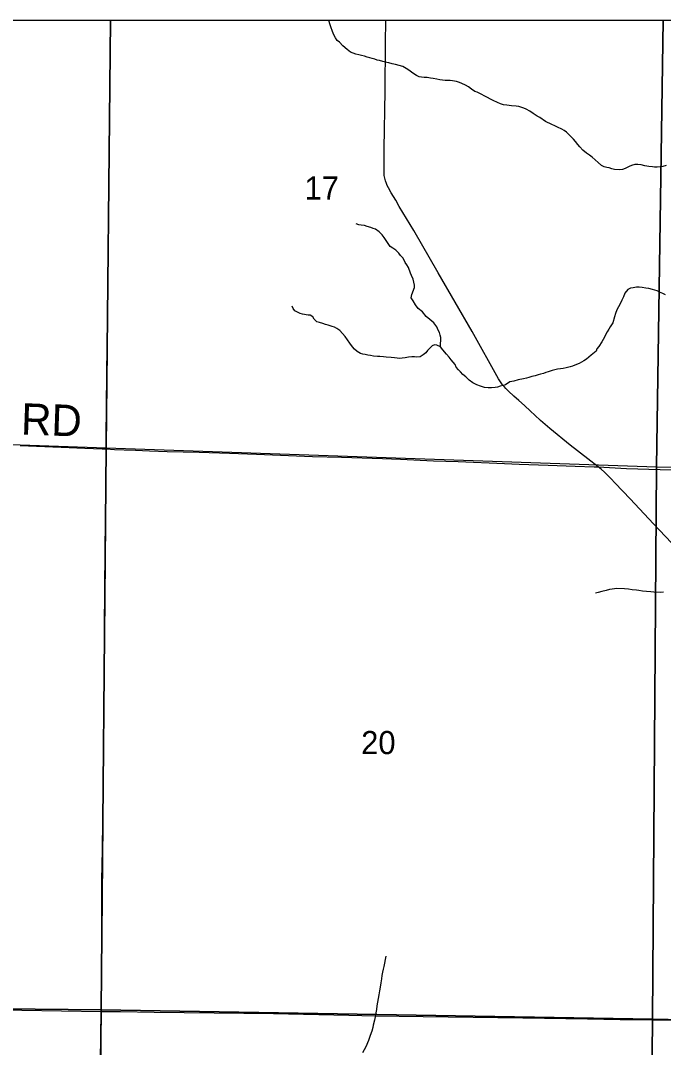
# Model space of a CAD drawing. Extents: x 0 to 34, y 0 to 22.
# Drawn here: x 27.506 to 28.088, y 19.307 to 20.236 of the extents above; entities that cross this region are included whole.
import ezdxf

# ---------------------------------------------------------------- set-up
doc = ezdxf.new("R2010")
doc.units = 0
for name, color, linetype in [('GM_X_Minor_River', 7, 'Continuous'), ('GM_X_Section', 7, 'Continuous'), ('GM_X_Section_Text', 7, 'Continuous'), ('GM_X_Township_Road', 7, 'Continuous'), ('GM_X_Township_Road_Text', 7, 'Continuous'), ('GM_X_Unincorporated', 7, 'Continuous'), ('SC_Scratch1', 7, 'Continuous'), ('SH_Border', 7, 'Continuous'), ('SH_Cut_Line', 7, 'Continuous')]:
    doc.layers.add(name, color=color, linetype=linetype)

msp = doc.modelspace()

# ---------------------------------------------------------------- linework, layer by layer
at = {"layer": 'GM_X_Minor_River'}
for points in [[(27.82658, 20.2012), (27.82431, 20.20183), (27.82224, 20.20245), (27.81978, 20.20309), (27.81714, 20.20391), (27.8145, 20.20455), (27.81224, 20.20518), (27.80959, 20.20582), (27.80695, 20.20664), (27.80451, 20.20766), (27.80153, 20.21001), (27.79762, 20.21316), (27.79466, 20.21646), (27.79261, 20.21804), (27.79096, 20.22036), (27.78951, 20.22306), (27.78846, 20.22632), (27.78685, 20.23055), (27.78578, 20.23305), (27.78546, 20.23534), (27.78502, 20.23613)], [(28.08999, 20.10513), (28.08711, 20.10406), (28.08463, 20.10375), (28.08196, 20.10343), (28.07968, 20.10349), (28.0776, 20.10392), (28.07438, 20.1042), (28.07078, 20.10486), (28.06738, 20.10552), (28.06454, 20.10597), (28.06188, 20.10604), (28.05881, 20.10497), (28.0567, 20.10408), (28.05304, 20.10227), (28.05073, 20.10137), (28.04769, 20.10107), (28.04352, 20.10156), (28.04106, 20.102), (28.03861, 20.10282), (28.03634, 20.10326), (28.03407, 20.1037), (28.03163, 20.10509), (28.02847, 20.10784), (28.02328, 20.11253), (28.02066, 20.1145), (28.01805, 20.11628), (28.01489, 20.11902), (28.01211, 20.12176), (28.01027, 20.12408), (28.00805, 20.12661), (28.00621, 20.12875), (28.00307, 20.13225), (27.99991, 20.13519), (27.99786, 20.13657), (27.9958, 20.13776), (27.99186, 20.13977), (27.98942, 20.14078), (27.9866, 20.14199), (27.98097, 20.1448), (27.97574, 20.14835), (27.97349, 20.14974), (27.96994, 20.15211), (27.96695, 20.15409), (27.96358, 20.15608), (27.96151, 20.15689), (27.95944, 20.15751), (27.95699, 20.15834), (27.95453, 20.15859), (27.95036, 20.15908), (27.946, 20.15957), (27.94297, 20.16002), (27.94033, 20.16085), (27.93751, 20.16206), (27.93357, 20.16388), (27.92607, 20.16787), (27.92288, 20.16966), (27.91931, 20.17128), (27.91705, 20.17209), (27.91406, 20.17407), (27.91145, 20.17604), (27.90864, 20.17763), (27.90545, 20.17924), (27.9032, 20.18024), (27.90037, 20.18088), (27.89697, 20.18173), (27.89488, 20.18197), (27.89241, 20.18185), (27.89032, 20.1819), (27.88785, 20.18215), (27.8854, 20.1826), (27.88256, 20.18324), (27.87953, 20.18369), (27.87688, 20.18414), (27.87404, 20.1846), (27.87138, 20.18466), (27.86892, 20.18491), (27.86684, 20.18535), (27.8644, 20.18636), (27.86178, 20.18795), (27.85972, 20.18952), (27.85749, 20.19129), (27.85487, 20.19288), (27.85206, 20.19447), (27.84867, 20.19551), (27.84546, 20.19635), (27.84243, 20.197), (27.83941, 20.19783), (27.83733, 20.19808), (27.83394, 20.19911), (27.83073, 20.19996), (27.82865, 20.20039), (27.82658, 20.2012)], [(27.99455, 19.92122), (27.99188, 19.9209), (27.98709, 19.9195), (27.98345, 19.91846), (27.98135, 19.91775), (27.97905, 19.91705), (27.97656, 19.91635), (27.97445, 19.91564), (27.97176, 19.91476), (27.96871, 19.91408), (27.96603, 19.91338), (27.96373, 19.91268), (27.96105, 19.91218), (27.95628, 19.91116), (27.95226, 19.91012), (27.94862, 19.90926), (27.94495, 19.9067), (27.94284, 19.90618), (27.93997, 19.90549), (27.93748, 19.9046), (27.93538, 19.90428), (27.93214, 19.90398), (27.9291, 19.90387), (27.92588, 19.90433), (27.92229, 19.90537), (27.9189, 19.9066), (27.91515, 19.90859), (27.91198, 19.91095), (27.90883, 19.91389), (27.90622, 19.91604), (27.9042, 19.91857), (27.90215, 19.92033), (27.90031, 19.92266), (27.89923, 19.92497), (27.89574, 19.92943), (27.89371, 19.93176), (27.89131, 19.93448), (27.88817, 19.93818), (27.88597, 19.94108), (27.88603, 19.94374), (27.88631, 19.94697), (27.88637, 19.94944), (27.88586, 19.95173), (27.88497, 19.95404), (27.88389, 19.95616), (27.88263, 19.95904), (27.88007, 19.96272), (27.87635, 19.96585), (27.87318, 19.9684), (27.86968, 19.97268), (27.86596, 19.97581), (27.86338, 19.97911), (27.86139, 19.98277), (27.85955, 19.98529), (27.86021, 19.98851), (27.86246, 19.99472), (27.86251, 19.99681), (27.86133, 20.00236), (27.85989, 20.00544), (27.859, 20.00774), (27.85722, 20.01273), (27.85557, 20.01505), (27.85411, 20.01718), (27.85231, 20.02122), (27.84991, 20.02375), (27.84844, 20.02588), (27.84547, 20.02843), (27.84285, 20.03021), (27.84061, 20.03178), (27.83859, 20.0345), (27.83695, 20.0372), (27.83493, 20.03991), (27.83328, 20.04224), (27.83069, 20.04496), (27.82714, 20.04734), (27.82507, 20.04815), (27.823, 20.04896), (27.81961, 20.05), (27.81734, 20.05063), (27.81431, 20.05108), (27.81223, 20.05133), (27.80978, 20.05215)], [(28.08942, 19.98801), (28.08698, 19.98921), (28.08416, 19.99061), (28.08191, 19.99162), (28.07776, 19.99287), (28.07436, 19.99372), (28.07171, 19.99416), (28.06849, 19.99463), (28.06565, 19.99489), (28.06337, 19.99495), (28.06031, 19.99445), (28.05783, 19.99395), (28.05552, 19.99286), (28.05277, 19.98951), (28.05154, 19.98612), (28.05013, 19.98311), (28.04833, 19.97936), (28.04694, 19.9773), (28.04554, 19.97448), (28.04431, 19.97109), (28.04348, 19.96826), (28.04201, 19.96279), (28.03944, 19.95905), (28.03824, 19.95699), (28.03685, 19.95455), (28.03325, 19.9478), (28.03186, 19.94555), (28.0291, 19.94144), (28.02733, 19.9392), (28.02689, 19.93712), (28.02224, 19.93344), (28.01796, 19.92994), (28.01565, 19.92847), (28.0114, 19.92592), (28.0089, 19.92503), (28.00545, 19.9236), (28.00315, 19.9229), (27.9997, 19.92203), (27.99683, 19.92135), (27.99455, 19.92122)], [(27.88597, 19.94108), (27.88278, 19.94269), (27.88069, 19.94274), (27.87857, 19.94184), (27.87624, 19.93981), (27.87429, 19.93777), (27.87271, 19.93572), (27.87038, 19.93368), (27.86767, 19.93185), (27.86463, 19.93174), (27.86254, 19.93198), (27.86007, 19.93185), (27.85702, 19.93155), (27.85396, 19.93106), (27.85148, 19.93074), (27.84901, 19.93061), (27.84674, 19.93086), (27.84427, 19.93111), (27.84143, 19.93137), (27.83687, 19.93168), (27.83441, 19.93193), (27.831, 19.93221), (27.82891, 19.93226), (27.82531, 19.93273), (27.82285, 19.93318), (27.8202, 19.93362), (27.81793, 19.93406), (27.81565, 19.93431), (27.81358, 19.93512), (27.81078, 19.9369), (27.80836, 19.93887), (27.80651, 19.941), (27.80394, 19.9443), (27.79992, 19.95049), (27.79752, 19.95321), (27.79511, 19.95574), (27.79231, 19.95752), (27.79006, 19.95872), (27.78798, 19.95934), (27.7844, 19.96058), (27.78195, 19.96121), (27.77969, 19.96202), (27.77649, 19.96306), (27.77403, 19.96369), (27.77181, 19.96603), (27.77054, 19.96815), (27.76829, 19.96954), (27.76621, 19.96978), (27.76129, 19.97067), (27.75921, 19.97129), (27.75714, 19.9721), (27.75433, 19.97369), (27.75287, 19.97582), (27.75178, 19.97794)], [(28.0319, 19.71971), (28.02846, 19.71885), (28.02616, 19.71815)], [(28.08776, 19.71905), (28.0851, 19.71893), (28.07903, 19.71927), (28.07618, 19.71953), (28.0722, 19.71983), (28.06859, 19.72011), (28.06538, 19.72076), (28.0633, 19.721), (28.0595, 19.72129), (28.0561, 19.72195), (28.0523, 19.72223), (28.04547, 19.72241), (28.04127, 19.72194), (28.03879, 19.72144), (28.03573, 19.72076), (28.0319, 19.71971)], [(27.83649, 19.38991), (27.83604, 19.38687), (27.83539, 19.38364), (27.83475, 19.38061), (27.83431, 19.37814), (27.83367, 19.37548), (27.83303, 19.37245), (27.83258, 19.3696), (27.83192, 19.3658), (27.83145, 19.362), (27.83079, 19.35858), (27.83033, 19.35516), (27.82967, 19.35155), (27.82902, 19.34832), (27.82856, 19.34509), (27.82811, 19.34186), (27.82765, 19.33863), (27.82699, 19.33502), (27.82635, 19.33199), (27.8251, 19.32744), (27.82467, 19.32535), (27.82383, 19.32213), (27.82241, 19.31835), (27.82078, 19.31362), (27.81855, 19.30796), (27.81557, 19.3025)]]:
    msp.add_lwpolyline(points, dxfattribs=at)
at = {"layer": 'GM_X_Section'}
for points in [[(27.10891, 19.86623), (27.58358, 19.8497), (27.57916, 19.34142), (27.10195, 19.34626), (27.10211, 19.36141)], [(27.58358, 19.8497), (28.08133, 19.83246), (28.07768, 19.33287), (27.57916, 19.34142)], [(28.08133, 19.83246), (28.58918, 19.82597), (28.58827, 19.32216), (28.07768, 19.33287)], [(27.10195, 19.34626), (27.57916, 19.34142), (27.57362, 18.84188), (27.09433, 18.85491)], [(27.57916, 19.34142), (28.07768, 19.33287), (28.07279, 18.82897), (27.57362, 18.84188)], [(28.07768, 19.33287), (28.58827, 19.32216), (28.58291, 18.82262), (28.07279, 18.82897)]]:
    msp.add_lwpolyline(points, close=True, dxfattribs=at)
at = {"layer": 'GM_X_Township_Road'}
for points in [[(27.57912, 19.34007), (27.57937, 19.35989), (27.57969, 19.39468), (27.57983, 19.45869), (27.58022, 19.48634), (27.58125, 19.56431), (27.5817, 19.62117), (27.58225, 19.68641), (27.58278, 19.75662), (27.5834, 19.81068), (27.58351, 19.84868), (27.58354, 19.85882), (27.58417, 19.91599), (27.5848, 19.96631), (27.58543, 20.01508), (27.58642, 20.10487), (27.58729, 20.18533), (27.58753, 20.23613)], [(28.12246, 19.73494), (28.07877, 19.78083), (28.0575, 19.80347), (28.04405, 19.81768), (28.03993, 19.8219), (28.03427, 19.82766), (28.03131, 19.83041), (28.02874, 19.83249), (28.01919, 19.83987), (28.00319, 19.8522), (27.98493, 19.86707), (27.97653, 19.87448), (27.97127, 19.87926), (27.96746, 19.88291), (27.96196, 19.88793), (27.95679, 19.89238), (27.95239, 19.89629), (27.94739, 19.90093), (27.94496, 19.90333), (27.94356, 19.90506), (27.9422, 19.90663), (27.94019, 19.90935), (27.93837, 19.91223), (27.9146, 19.9548), (27.88377, 20.00803), (27.86177, 20.04612), (27.84878, 20.06806), (27.8455, 20.07357), (27.8413, 20.08039), (27.83886, 20.08469), (27.83779, 20.08693), (27.83708, 20.08865), (27.83618, 20.09129), (27.83556, 20.0937), (27.83521, 20.09584), (27.83498, 20.09894), (27.83507, 20.12038), (27.83597, 20.17224), (27.83632, 20.21572), (27.8366, 20.23613)], [(27.5059, 19.85181), (27.54297, 19.85029), (27.56446, 19.84951), (27.58004, 19.84885), (27.58351, 19.84868), (27.5911, 19.84832), (27.60006, 19.84791), (27.61005, 19.84754), (27.62295, 19.84708), (27.6389, 19.84653), (27.66779, 19.84565), (27.69513, 19.84487), (27.71966, 19.84384), (27.74852, 19.84269), (27.77022, 19.84195), (27.79652, 19.84113), (27.83355, 19.84002), (27.84979, 19.8394), (27.87975, 19.83808), (27.90199, 19.83722), (27.94399, 19.83548), (27.95703, 19.83502), (27.98341, 19.83399), (28.00793, 19.83299), (28.02496, 19.83258), (28.02874, 19.83249)], [(28.02874, 19.83249), (28.05415, 19.83114), (28.08461, 19.83017), (28.1151, 19.82951)], [(27.4562, 19.34171), (27.50745, 19.34112), (27.57912, 19.34007), (27.59658, 19.33991), (27.62702, 19.33948), (27.68138, 19.33879), (27.73511, 19.33799), (27.80314, 19.33664), (27.82674, 19.33611), (27.87022, 19.33549), (27.96049, 19.33408), (28.01901, 19.33332), (28.04852, 19.33276), (28.1059, 19.33211)], [(27.57855, 19.29499), (27.57912, 19.34007)]]:
    msp.add_lwpolyline(points, dxfattribs=at)
at = {"layer": 'GM_X_Unincorporated'}
for points in [[(27.58753, 20.23613), (27.11464, 20.23613), (27.10891, 19.86623), (27.58358, 19.8497)], [(28.08737, 20.23613), (27.58753, 20.23613), (27.58358, 19.8497), (28.08133, 19.83246)], [(28.59162, 20.23613), (28.08737, 20.23613), (28.08133, 19.83246), (28.58918, 19.82597)]]:
    msp.add_lwpolyline(points, close=True, dxfattribs=at)
at = {"layer": 'SC_Scratch1'}
msp.add_lwpolyline([(30.09296, 20.23613), (27.11465, 20.23613), (27.11278, 20.11735), (27.11275, 20.11553), (27.11156, 20.03143), (27.10896, 19.86503), (27.10075, 19.3521), (27.10072, 19.35026), (27.09546, 18.98704)], dxfattribs=at)
at = {"layer": 'SH_Border'}
msp.add_lwpolyline([(23.89999, 20.23613), (23.89999, 13.43613), (30.69999, 13.43613), (30.69999, 20.23613)], close=True, dxfattribs=at)
at = {"layer": 'SH_Cut_Line'}
msp.add_lwpolyline([(30.09296, 20.23613), (23.89999, 20.23613)], dxfattribs=at)

# ---------------------------------------------------------------- texts
at = {"layer": 'GM_X_Section_Text'}
for s, p in [('17', (27.763, 20.07419)), ('20', (27.81425, 19.57268))]:
    msp.add_text(s, height=0.020928, rotation=0.00001, dxfattribs=at).set_placement(p)
at = {"layer": 'GM_X_Township_Road_Text'}
msp.add_text('RD', height=0.028409, rotation=358.02429, dxfattribs=at).set_placement((27.5063, 19.86173))

doc.saveas('drawing.dxf')
